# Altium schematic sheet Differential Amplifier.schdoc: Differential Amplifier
size A4; Organization: Altium Limited; Address1: L3, 12a Rodborough Rd; Address2: Frenchs Forest; Address3: NSW; Address4: Australia 2086; DocumentNumber: 1; SheetNumber: 1; SheetTotal: 1
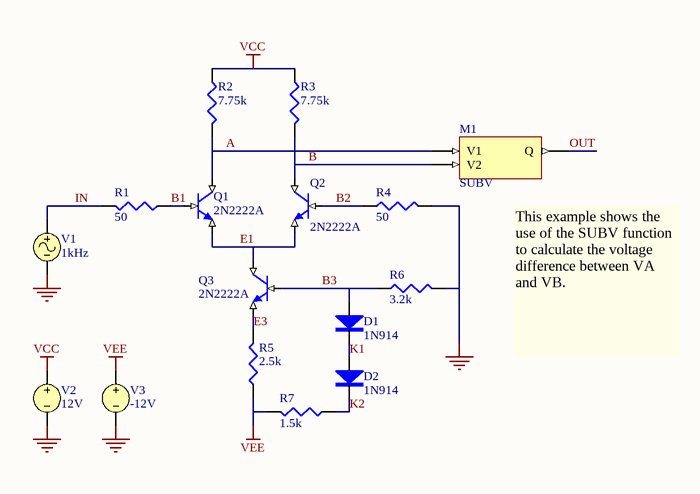
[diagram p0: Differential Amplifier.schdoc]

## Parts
D1  1N914
D2  1N914
M1  SUBV
Q1  2N2222A
Q2  2N2222A
Q3  2N2222A
R1  50
R2  7.75k
R3  7.75k
R4  50
R5  2.5k
R6  3.2k
R7  1.5k
V1  1kHz
V2  12V
V3  -12V

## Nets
GND: R4.1(TOP) R6.1(TOP) V1.2 V2.2 V3.2
VCC: R2.2(BOT) R3.2(BOT) V2.1
VEE: R5.2(BOT) R7.1(TOP) V3.1
A: M1.1(V1) Q1.1(C) R2.1(TOP)
B: M1.2(V2) Q2.1(C) R3.1(TOP)
B1: Q1.2(B) R1.2(BOT)
B2: Q2.2(B) R4.2(BOT)
B3: D1.1(A) Q3.2(B) R6.2(BOT)
E1: Q1.3(E) Q2.3(E) Q3.1(C)
E3: Q3.3(E) R5.1(TOP)
IN: R1.1(TOP) V1.1
K1: D1.2(K) D2.1(A)
K2: D2.2(K) R7.2(BOT)
OUT: M1.3(Q)

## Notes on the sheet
- (near M1) This example shows the use of the SUBV function to calculate the voltage difference between VA and VB.

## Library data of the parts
D1 D2 = 1N914: Diode
M1 = SUBV: Subtract Voltages
Q1-Q3 = 2N2222A: NPN BJT
R1-R7 = RES: Resistor
V1 = VSIN: Sinusoidal Voltage Source
V2 V3 = VSRC: Voltage Source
